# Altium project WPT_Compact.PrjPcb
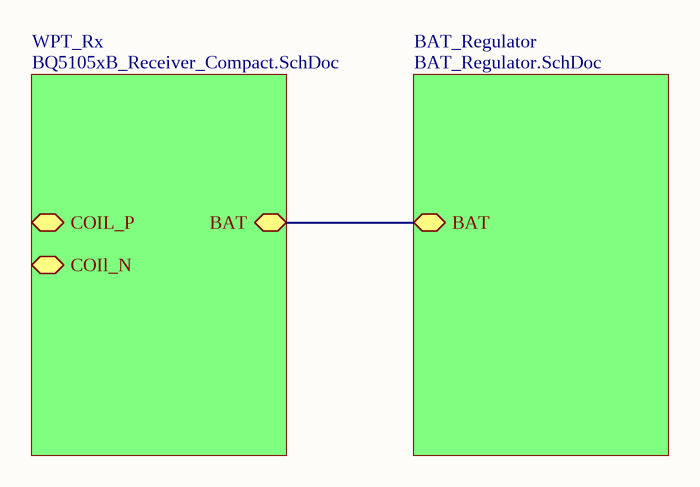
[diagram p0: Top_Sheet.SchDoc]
3 sheets, 33 parts. Net scope: hierarchical (ports join the sheet entries above them; power ports are global).
Board file: WPT_Compact.PcbDoc
Sheets:
  Top_Sheet.SchDoc
    WPT_Rx = BQ5105xB_Receiver_Compact.SchDoc
    BAT_Regulator = BAT_Regulator.SchDoc

## Sheet Top_Sheet.SchDoc
size A

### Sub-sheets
BAT_Regulator = BAT_Regulator.SchDoc: BAT
WPT_Rx = BQ5105xB_Receiver_Compact.SchDoc: BAT, COIL_P, COIl_N

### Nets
NetC9_1: sheet WPT_Rx/BAT, sheet BAT_Regulator/BAT

## Sheet BQ5105xB_Receiver_Compact.SchDoc
size 431 x 279 mm; Date: Not shown in title block; ApprovedBy: Not shown in title block; CheckedBy: Not shown in title block; Author: Not shown in title block; CompanyName: Not shown in title block; Engineer: Not shown in title block; Organization: Not shown in title block; Address1: Not shown in title block; Address2: Not shown in title block; Address3: Not shown in title block; Address4: Not shown in title block; DocumentNumber: 1; Revision: Use project parameter SCH_Rev; SheetNumber: 1; SheetTotal: 1; PageSetup: Record=PageOptions¦CenterHorizontal=True¦CenterVertical=True¦PrintScale=2.24¦XCorrection=1.00¦YCorrection=1.00¦PrintKind=0¦BorderSize=5000000¦LeftOffset=0¦BottomOffset=0¦Orientation=2¦PaperLength=1000¦PaperWidth=1000¦Scale=100¦PaperSource=15¦PrintQuality=600¦MediaType=1¦DitherType=10¦PaperKind=11x17¦PrintScaleMode=1
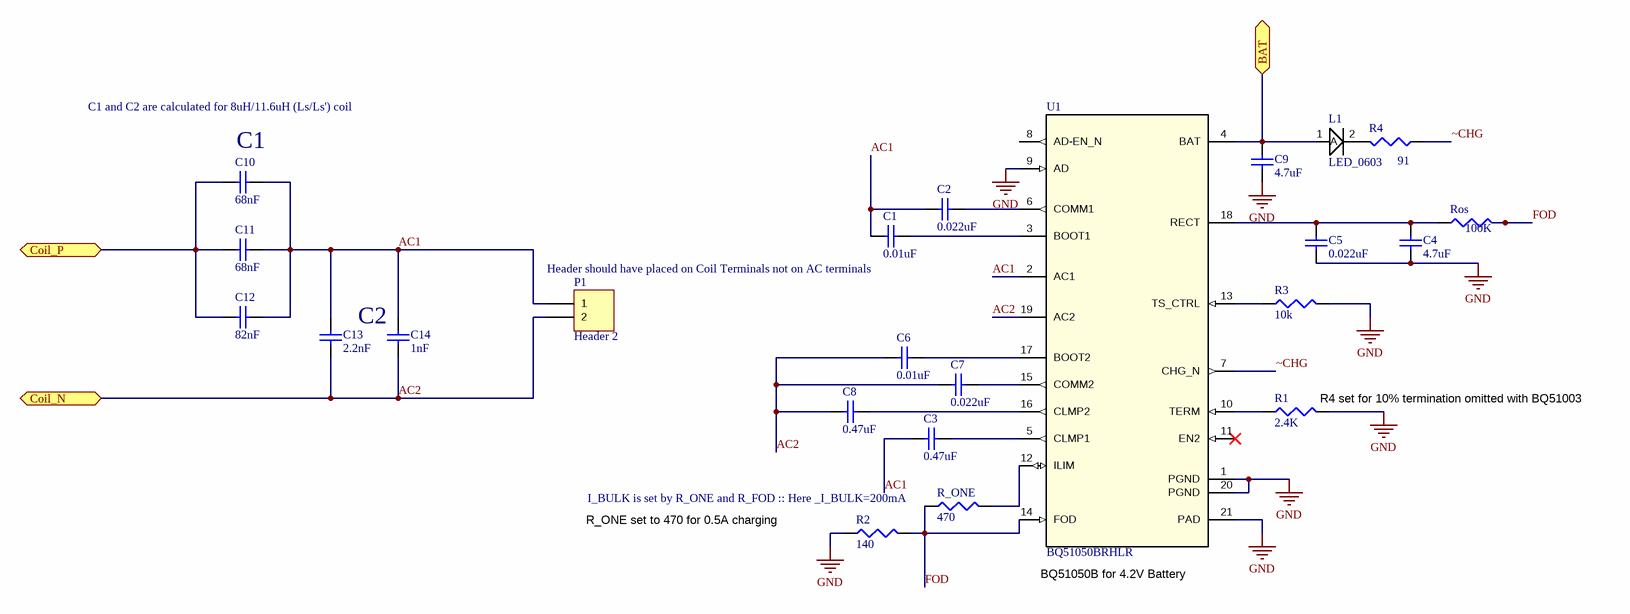
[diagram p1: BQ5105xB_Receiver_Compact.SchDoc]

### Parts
C1  0.01uF  [0402]
C2  0.022uF  [0402]
C3  0.47uF  [0402]
C4  4.7uF  [1608[0603]]
C5  0.022uF  [0402]
C6  0.01uF  [0402]
C7  0.022uF  [0402]
C8  0.47uF  [0402]
C9  4.7uF  [1608[0603]]
C10  68nF  [0402]
C11  68nF  [0402]
C12  82nF  [0402]
C13  2.2nF  [0402]
C14  1nF  [0402]
L1  LED_0603  [LED_0603]
P1  Header 2  [HDR1X2]
R1  2.4K  [J1-0603]
R2  140  [J1-0603]
R3  10k  [J1-0603]
R4  91  [J1-0603]
R_ONE  470  [J1-0603]
Ros  100K  [J1-0603]
U1  BQ51050BRHLR  [RHL0020A]

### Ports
BAT, Coil_N, Coil_P

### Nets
GND: C4.2 C5.2 C9.2 R1.2 R2.1 R3.2 U1.1(PGND) U1.9(AD) U1.20(PGND) U1.21(PAD)
AC1: C1.1 C2.2 C3.2 C10.1 C11.1 C12.1 C13.2 C14.2 P1.1 U1.2(AC1)
AC2: C6.1 C7.2 C8.2 C13.1 C14.1 P1.2 U1.19(AC2) ; port Coil_N
FOD: R2.2 R_ONE.1 Ros.1 U1.14(FOD)
~CHG: R4.1 U1.7(CHG_N)
NetC1_2: C1.2 U1.3(BOOT1)
NetC2_1: C2.1 U1.6(COMM1)
NetC3_1: C3.1 U1.5(CLMP1)
NetC4_1: C4.1 C5.1 Ros.2 U1.18(RECT)
NetC6_2: C6.2 U1.17(BOOT2)
NetC7_1: C7.1 U1.15(COMM2)
NetC8_1: C8.1 U1.16(CLMP2)
NetC9_1: C9.1 L1.1(A) U1.4(BAT) ; port BAT
NetC10_2: C10.2 C11.2 C12.2 ; port Coil_P
NetL1_2: L1.2(C) R4.2
NetR1_1: R1.1 U1.10(TERM)
NetR3_1: R3.1 U1.13(TS_CTRL)
NetR_ONE_2: R_ONE.2 U1.12(ILIM)

Not connected (* = marked no-connect by the designer): U1 8(AD-EN_N) 11(EN2)*

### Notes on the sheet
- C1 and C2 are calculated for 8uH/11.6uH (Ls/Ls') coil
- (near C10) C1
- C2
- Header should have placed on Coil Terminals not on AC terminals
- (near R1) R4 set for 10% termination omitted with BQ51003
- I_BULK is set by R_ONE and R_FOD :: Here _I_BULK=200mA
- R_ONE set to 470 for 0.5A charging
- (near U1) BQ51050B for 4.2V Battery

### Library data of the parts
C1-C14 = Cap Semi: Capacitor (Semiconductor SIM Model)
P1 = Header 2: Header, 2-Pin
R1-R4 R_ONE Ros = Res3: Resistor
U1 = BQ51050BRHLR: Imported; Manufacturer: Texas Instruments; CompType: IC; PIN_COUNT: 21

## Sheet BAT_Regulator.SchDoc
size A
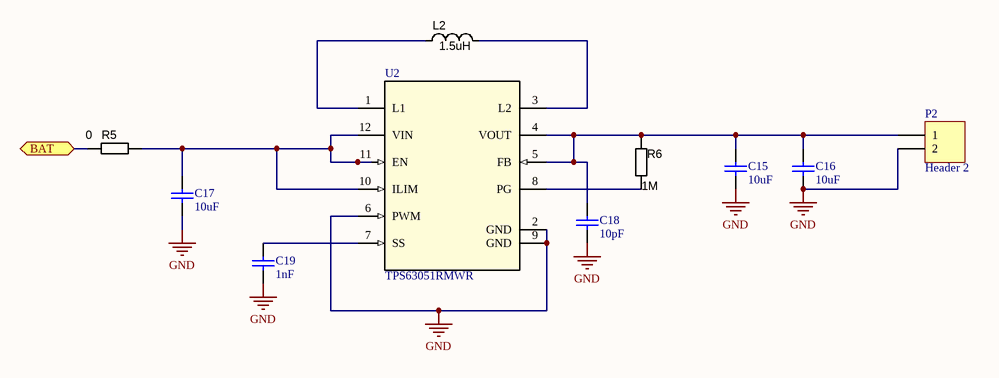
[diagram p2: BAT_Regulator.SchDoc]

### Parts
C15  10uF  [1608[0603]]
C16  10uF  [1608[0603]]
C17  10uF  [1608[0603]]
C18  10pF  [0402]
C19  1nF  [0402]
L2  1.5uH  [INDM2520X190N]
P2  Header 2  [HDR1X2]
R5  0  [RESC1005X40N]
R6  1M  [RESC1608N_ZERO]
U2  TPS63051RMWR  [RMW0012A]

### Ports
BAT

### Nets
GND: C15.1 C16.1 C17.1 C18.1 C19.1 P2.2 U2.2(GND) U2.6(PWM) U2.9(GND)
NetC9_1: R5.1 ; port BAT
NetC15_2: C15.2 C16.2 C18.2 P2.1 R6.1 U2.4(VOUT) U2.5(FB)
NetC17_2: C17.2 R5.2 U2.10(ILIM) U2.11(EN) U2.12(VIN)
NetC19_2: C19.2 U2.7(SS)
NetL2_1: L2.1 U2.1(L1)
NetL2_2: L2.2 U2.3(L2)
NetR6_2: R6.2 U2.8(PG)

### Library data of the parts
C15-C19 = Cap Semi: Capacitor (Semiconductor SIM Model)
L2 = INDC_47n_1008_1A: Inductor SMD chip 47nH 1008; Manufacturer 1: Abracon Corporation; Manufacturer Part Number 1: AISC-1008-R047J-T; Ratings: 1 A; Tolerance: ±5%; Material: Ceramic; DC Resistance (DCR): 160 mOhm Max; SCDType: source
P2 = Header 2: Header, 2-Pin
R5 = RES_1K_0402_5%: Resistor SMD chip 1k Ohm 0.063W 5% 0402; Manufacturer 1: Yageo; Manufacturer Part Number 1: RC0402JR-071KL; Ratings: 1/16 W; SCDType: spec
R6 = RES_0R_0603: Resistor SMD chip 0.0 Ohm 0.1W 0603; Manufacturer 1: Vishay/Dale; Manufacturer Part Number 1: CRCW06030000Z0EA; Tolerance: ±5%; Ratings: 1/10W; SCDType: spec
U2 = TPS63051RMWR: Imported; Alternate_PartNumber: TPS63051RMWT; Manufacturer: Texas Instruments; CompType: IC; PIN_COUNT: 12

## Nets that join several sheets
GND: BQ5105xB_Receiver_Compact (10 pins), BAT_Regulator (9 pins)
NetC9_1: BQ5105xB_Receiver_Compact (C9.1 L1.1 U1.4), BAT_Regulator (R5.1)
